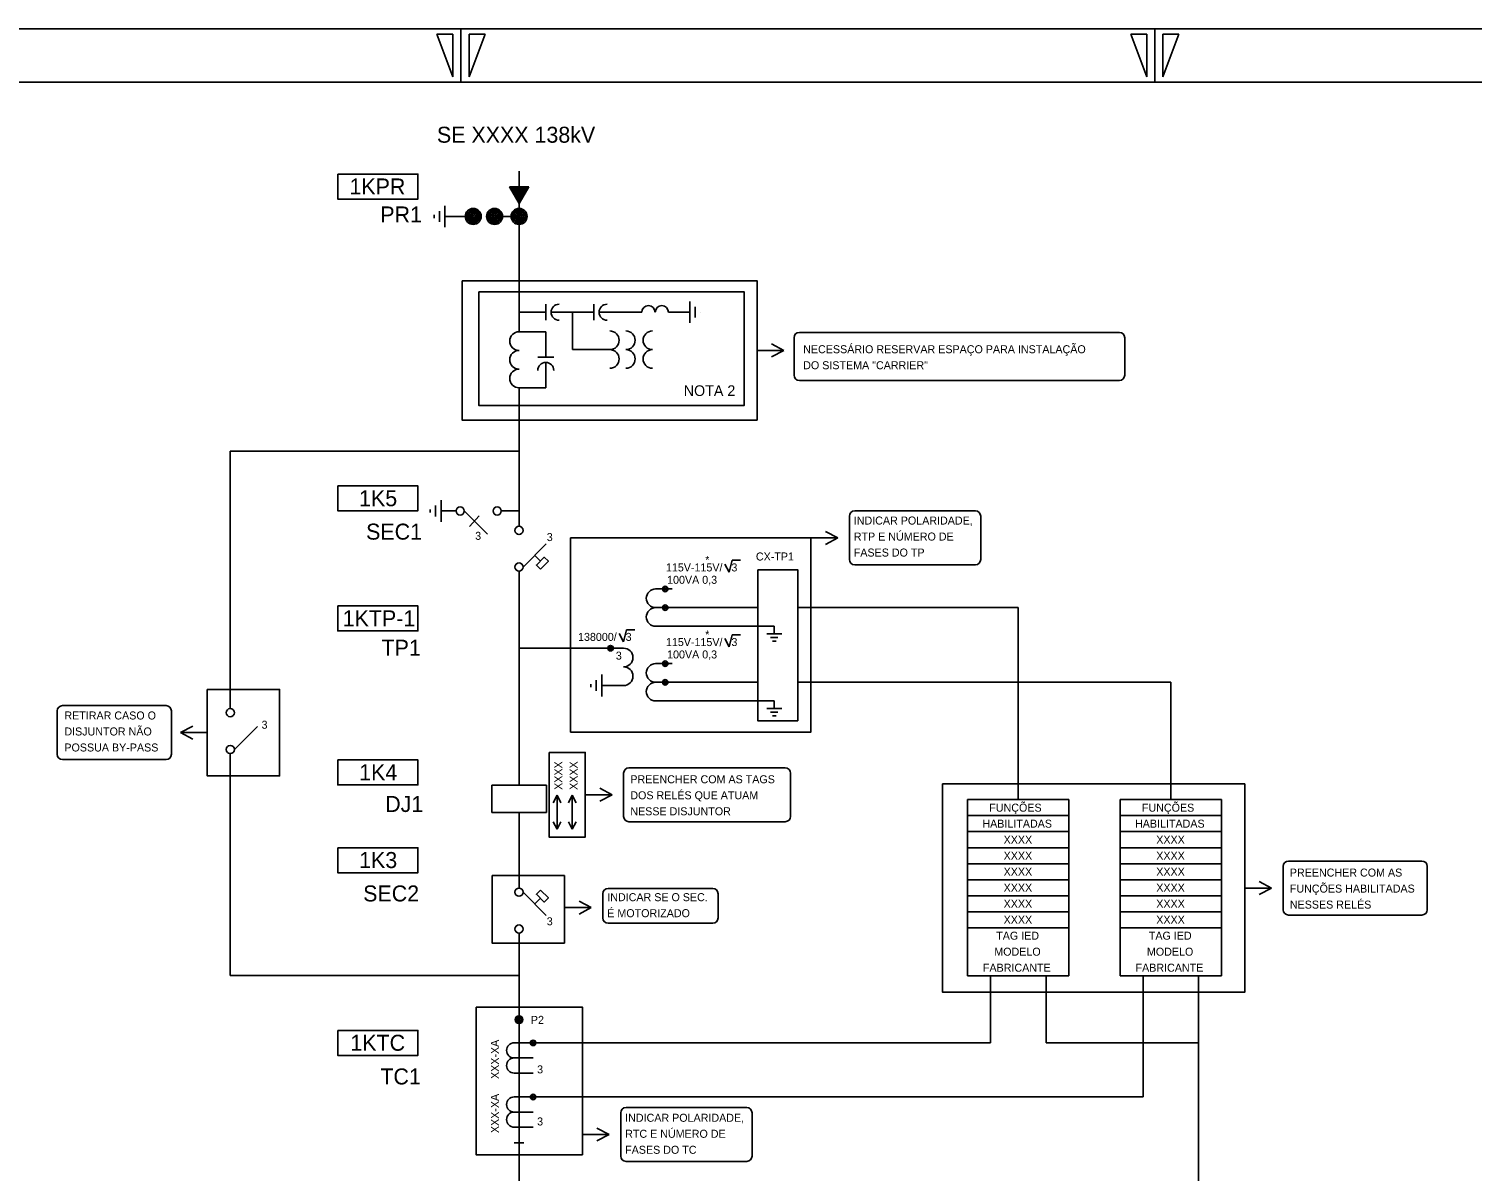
# Model space of a CAD drawing. Extents: x 563 to 1404, y 358 to 952.
# Drawn here: x 822.6 to 1093.1, y 737.8 to 952 of the extents above; entities that cross this region are included whole.
import ezdxf

# ---------------------------------------------------------------- set-up
doc = ezdxf.new("R2010")
doc.units = 0
doc.layers.add('Level 1', color=7, linetype='Continuous')
doc.layers.add('New Level (0)', color=7, linetype='Continuous')

# ---------------------------------------------------------------- blocks, each defined once
blk = doc.blocks.new('_U3')
for p, q in [((-1.47, 0.42), (-0.62, -1.12)), ((-0.62, -1.12), (-0.07, 1.12)), ((-0.07, 1.12), (1.47, 1.12))]:
    blk.add_line(p, q)

msp = doc.modelspace()

# ---------------------------------------------------------------- linework, layer by layer
for p, q in [((914.46, 925.28), (914.46, 895.18)), ((916.27, 922.35), (912.65, 922.35)), ((912.65, 922.35), (914.46, 919.25)), ((916.27, 922.35), (912.65, 922.35)), ((916.08, 922.25), (912.83, 922.25)), ((912.83, 922.25), (914.46, 919.46)), ((914.46, 919.25), (916.27, 922.35)), ((914.46, 922.35), (914.46, 919.25)), ((914.46, 919.46), (916.08, 922.25)), ((915.9, 922.14), (913.01, 922.14)), ((913.01, 922.14), (914.46, 919.67)), ((915.72, 922.04), (913.19, 922.04)), ((913.19, 922.04), (914.46, 919.87)), ((915.54, 921.94), (913.37, 921.94)), ((913.37, 921.94), (914.46, 920.08)), ((915.36, 921.83), (913.55, 921.83)), ((913.55, 921.83), (914.46, 920.29)), ((915.18, 921.73), (913.73, 921.73)), ((913.73, 921.73), (914.46, 920.49)), ((915, 921.63), (913.91, 921.63)), ((913.91, 921.63), (914.46, 920.7)), ((914.82, 921.52), (914.09, 921.52)), ((914.09, 921.52), (914.46, 920.9)), ((914.64, 921.42), (914.27, 921.42)), ((914.27, 921.42), (914.46, 921.11)), ((914.46, 919.67), (915.9, 922.14)), ((914.46, 919.87), (915.72, 922.04)), ((914.46, 920.08), (915.54, 921.94)), ((914.46, 920.29), (915.36, 921.83)), ((914.46, 920.49), (915.18, 921.73)), ((914.46, 920.7), (915, 921.63)), ((914.46, 920.9), (914.82, 921.52)), ((914.46, 921.11), (914.64, 921.42)), ((898.55, 917.1), (898.55, 916.5)), ((899.55, 917.8), (899.55, 915.8)), ((900.55, 914.8), (900.55, 918.8)), ((898.55, 916.8), (898.55, 916.8)), ((901.87, 916.8), (900.55, 916.8)), ((905.87, 916.8), (901.87, 916.8)), ((914.46, 916.8), (909.87, 916.8)), ((914.46, 884.68), (914.46, 858.71)), ((914.46, 872.79), (860.34, 872.79)), ((860.34, 824.54), (860.34, 872.79)), ((899.86, 863.64), (899.86, 859.55)), ((897.82, 861.83), (897.82, 861.3)), ((898.83, 860.57), (898.83, 862.62)), ((902.65, 861.59), (899.86, 861.59)), ((908.52, 857.25), (904.18, 861.59)), ((905.18, 858.65), (906.97, 860.67)), ((914.46, 861.59), (911.13, 861.59)), ((919.56, 855.41), (915.22, 851.07)), ((918.45, 852.18), (917.39, 853.24)), ((914.46, 810.18), (914.46, 850.27)), ((940.05, 846.96), (943.16, 846.96)), ((940.05, 843.46), (959.19, 843.46)), ((966.67, 843.46), (1008, 843.46)), ((940.05, 839.96), (962.28, 839.96)), ((963.68, 838.56), (960.88, 838.56)), ((962.28, 839.96), (962.28, 838.56)), ((914.46, 835.86), (934.05, 835.86)), ((961.58, 837.86), (962.98, 837.86)), ((961.94, 837.16), (962.62, 837.16)), ((940.05, 832.97), (943.16, 832.97)), ((929.96, 830.91), (929.96, 826.82)), ((927.92, 829.1), (927.92, 828.57)), ((928.93, 827.84), (928.93, 829.89)), ((934.05, 828.86), (929.96, 828.86)), ((940.05, 829.47), (943.16, 829.47)), ((940.05, 829.47), (959.19, 829.47)), ((966.67, 829.47), (1036.6, 829.47)), ((940.05, 825.97), (962.28, 825.97)), ((962.28, 825.97), (962.28, 824.57)), ((963.68, 824.57), (960.88, 824.57)), ((961.58, 823.87), (962.98, 823.87)), ((961.94, 823.17), (962.62, 823.17)), ((865.45, 821.2), (861.11, 816.87)), ((860.34, 774.5), (860.34, 816.1)), ((909.34, 805.06), (909.34, 810.18)), ((909.34, 810.18), (919.58, 810.18)), ((919.58, 810.18), (919.58, 805.06)), ((921.57, 808.3), (920.86, 806.88)), ((921.57, 801.93), (921.57, 808.3)), ((921.57, 808.3), (922.28, 806.88)), ((924.42, 808.3), (923.71, 806.88)), ((924.42, 801.93), (924.42, 808.3)), ((924.42, 808.3), (925.13, 806.88)), ((1017.49, 807.47), (998.51, 807.47)), ((998.51, 807.47), (998.51, 774.47)), ((1017.49, 807.47), (1017.49, 774.47)), ((1046.09, 807.47), (1027.11, 807.47)), ((1027.11, 807.47), (1027.11, 774.47)), ((1046.09, 807.47), (1046.09, 774.47)), ((919.58, 805.06), (909.34, 805.06)), ((914.46, 790.89), (914.46, 805.06)), ((921.57, 801.93), (920.86, 803.34)), ((921.57, 801.93), (922.28, 803.34)), ((924.42, 801.93), (923.71, 803.34)), ((924.42, 801.93), (925.13, 803.34)), ((1017.49, 804.47), (998.51, 804.47)), ((1046.09, 804.47), (1027.11, 804.47)), ((1017.49, 801.47), (998.51, 801.47)), ((1046.09, 801.47), (1027.11, 801.47)), ((1017.49, 798.47), (998.51, 798.47)), ((1046.09, 798.47), (1027.11, 798.47)), ((1017.49, 795.47), (998.51, 795.47)), ((1046.09, 795.47), (1027.11, 795.47)), ((1017.49, 792.47), (998.51, 792.47)), ((1046.09, 792.47), (1027.11, 792.47)), ((919.56, 785.78), (915.22, 790.12)), ((918.45, 789.02), (917.39, 787.95)), ((1017.49, 789.47), (998.51, 789.47)), ((1017.49, 789.47), (998.51, 789.47)), ((1046.09, 789.47), (1027.11, 789.47)), ((1046.09, 789.47), (1027.11, 789.47)), ((1017.49, 786.47), (998.51, 786.47)), ((1046.09, 786.47), (1027.11, 786.47)), ((914.46, 680.4), (914.46, 782.45)), ((1017.49, 783.47), (998.51, 783.47)), ((1046.09, 783.47), (1027.11, 783.47)), ((914.46, 774.5), (860.34, 774.5)), ((1017.49, 774.47), (998.51, 774.47)), ((1046.09, 774.47), (1027.11, 774.47)), ((913.55, 761.88), (917.09, 761.88)), ((917.09, 761.88), (1002.8, 761.88)), ((1013.2, 761.88), (1041.8, 761.88)), ((913.55, 759.05), (917.09, 759.05)), ((913.55, 756.22), (917.09, 756.22)), ((913.55, 751.74), (917.09, 751.74)), ((917.09, 751.74), (1031.4, 751.74)), ((913.55, 748.91), (917.09, 748.91)), ((913.55, 746.08), (917.09, 746.08))]:
    msp.add_line(p, q)
for points in [[(918.48, 850.68), (917.72, 851.45), (919.19, 852.92), (919.96, 852.15)], [(918.48, 790.52), (917.72, 789.75), (919.19, 788.28), (919.96, 789.05)]]:
    msp.add_lwpolyline(points, close=True)
for centre, radius in [((905.87, 916.8), 1.5), ((905.87, 916.8), 1.25), ((905.87, 916.8), 1), ((905.87, 916.8), 0.75), ((905.87, 916.8), 0.5), ((905.87, 916.8), 0.25), ((909.87, 916.8), 1.5), ((909.87, 916.8), 1.25), ((909.87, 916.8), 1), ((909.87, 916.8), 0.75), ((909.87, 916.8), 0.5), ((909.87, 916.8), 0.25), ((914.46, 916.8), 1.5), ((914.46, 916.8), 1.25), ((914.46, 916.8), 1), ((914.46, 916.8), 0.75), ((914.46, 916.8), 0.5), ((914.46, 916.8), 0.25), ((903.42, 861.59), 0.768), ((910.36, 861.59), 0.768), ((914.46, 857.94), 0.768), ((914.46, 851.07), 0.768), ((941.85, 846.96), 0.511), ((941.85, 846.96), 0.288), ((941.85, 843.46), 0.511), ((941.85, 843.46), 0.288), ((931.61, 835.86), 0.511), ((931.61, 835.86), 0.288), ((941.85, 832.97), 0.511), ((941.85, 832.97), 0.288), ((941.85, 829.47), 0.511), ((941.85, 829.47), 0.288), ((860.34, 823.77), 0.768), ((860.34, 816.87), 0.768), ((914.46, 790.12), 0.768), ((914.46, 783.22), 0.768), ((914.45, 766.22), 0.729), ((914.46, 766.21), 0.511), ((914.46, 766.21), 0.288), ((917.09, 761.88), 0.511), ((917.09, 761.88), 0.288), ((917.09, 751.74), 0.511), ((917.09, 751.74), 0.288)]:
    msp.add_circle(centre, radius)
for centre, radius, start, end in [((940.05, 845.21), 1.75, 90, 270), ((940.05, 841.71), 1.75, 90, 270), ((934.05, 834.11), 1.75, 270, 90), ((940.05, 831.22), 1.75, 90, 270), ((934.05, 830.61), 1.75, 270, 90), ((940.05, 827.72), 1.75, 90, 270), ((913.55, 760.47), 1.42, 90, 270), ((913.55, 757.63), 1.42, 90, 270), ((913.55, 750.33), 1.42, 90, 270), ((913.55, 747.5), 1.42, 90, 270)]:
    msp.add_arc(centre, radius, start, end)
at = {"layer": 'Level 1'}
for p, q in [((946.46, 900.83), (946.46, 896.83)), ((914.46, 898.83), (919.46, 898.83)), ((919.46, 900.33), (919.46, 897.33)), ((920.46, 898.83), (928.46, 898.83)), ((924.46, 898.83), (924.46, 891.83)), ((928.46, 900.33), (928.46, 897.33)), ((929.46, 898.83), (937.46, 898.83)), ((942.46, 898.83), (946.46, 898.83)), ((947.46, 897.83), (947.46, 899.83)), ((948.46, 898.83), (948.46, 898.83)), ((919.46, 895.18), (914.46, 895.18)), ((919.46, 890.43), (919.46, 895.18)), ((917.96, 890.43), (920.96, 890.43)), ((924.46, 891.83), (931.46, 891.83)), ((919.46, 884.68), (919.46, 889.43)), ((914.46, 884.68), (919.46, 884.68))]:
    msp.add_line(p, q, dxfattribs=at)
for centre, radius, start, end in [((921.96, 898.83), 1.5, 90, 270), ((930.96, 898.83), 1.5, 90, 270), ((938.71, 898.83), 1.25, 0, 180), ((941.21, 898.83), 1.25, 0, 180), ((914.46, 893.43), 1.75, 90, 270), ((931.46, 893.58), 1.75, 270, 90), ((934.46, 893.58), 1.75, 270, 90), ((939.46, 893.58), 1.75, 90, 270), ((914.46, 889.93), 1.75, 90, 270), ((931.46, 890.08), 1.75, 270, 90), ((934.46, 890.08), 1.75, 270, 90), ((939.46, 890.08), 1.75, 90, 270), ((914.46, 886.43), 1.75, 90, 270), ((919.46, 887.93), 1.5, 0, 180)]:
    msp.add_arc(centre, radius, start, end, dxfattribs=at)
at = {"layer": 'New Level (0)'}
for p, q in [((1403.58, 951.96), (562.58, 951.96)), ((1403.58, 951.96), (562.58, 951.96)), ((902.08, 950.96), (899.08, 950.96)), ((899.08, 950.96), (902.08, 942.96)), ((902.08, 942.96), (902.08, 950.96)), ((903.58, 951.96), (903.58, 941.96)), ((905.08, 942.96), (905.08, 950.96)), ((905.08, 950.96), (908.08, 950.96)), ((908.08, 950.96), (905.08, 942.96)), ((1032.08, 950.96), (1029.08, 950.96)), ((1029.08, 950.96), (1032.08, 942.96)), ((1032.08, 942.96), (1032.08, 950.96)), ((1033.58, 951.96), (1033.58, 941.96)), ((1035.08, 942.96), (1035.08, 950.96)), ((1035.08, 950.96), (1038.08, 950.96)), ((1038.08, 950.96), (1035.08, 942.96)), ((1393.58, 941.96), (572.58, 941.96)), ((964.08, 891.68), (961.78, 892.89)), ((965.99, 887.03), (965.99, 894.06)), ((966.99, 895.06), (997.07, 895.06)), ((997.07, 895.06), (1026.95, 895.06)), ((1027.95, 894.06), (1027.95, 887.03)), ((959.05, 891.68), (964.08, 891.68)), ((964.08, 891.68), (961.78, 890.48)), ((1026.95, 886.03), (966.99, 886.03)), ((976.35, 852.49), (976.35, 860.6)), ((977.35, 861.6), (984.7, 861.6)), ((984.7, 861.6), (999.96, 861.6)), ((1000.96, 860.6), (1000.96, 852.49)), ((974.19, 856.54), (971.89, 857.75)), ((969.16, 856.54), (974.19, 856.54)), ((974.19, 856.54), (971.89, 855.33)), ((999.96, 851.49), (977.35, 851.49)), ((1008, 843.46), (1008, 807.47)), ((1036.6, 829.47), (1036.6, 807.47)), ((828.91, 825.1), (832.67, 825.1)), ((832.67, 825.1), (848.31, 825.1)), ((827.91, 815.98), (827.91, 824.1)), ((849.31, 824.1), (849.31, 815.98)), ((851.01, 820.04), (853.31, 821.25)), ((856.04, 820.04), (851.01, 820.04)), ((851.01, 820.04), (853.31, 818.83)), ((848.31, 814.98), (828.91, 814.98)), ((934.05, 804.33), (934.05, 812.44)), ((935.05, 813.44), (942.4, 813.44)), ((942.4, 813.44), (964.34, 813.44)), ((965.34, 812.44), (965.34, 804.33)), ((931.89, 808.39), (929.59, 809.6)), ((926.86, 808.39), (931.89, 808.39)), ((931.89, 808.39), (929.59, 807.18)), ((964.34, 803.33), (935.05, 803.33)), ((1058.63, 795.96), (1065.98, 795.96)), ((1065.98, 795.96), (1083.64, 795.96)), ((1057.63, 786.84), (1057.63, 794.96)), ((1084.64, 794.96), (1084.64, 786.84)), ((930.16, 785.29), (930.16, 789.84)), ((931.16, 790.84), (938.51, 790.84)), ((938.51, 790.84), (950.74, 790.84)), ((951.74, 789.84), (951.74, 785.29)), ((1050.44, 790.9), (1055.47, 790.9)), ((1055.47, 790.9), (1053.17, 792.11)), ((1055.47, 790.9), (1053.17, 789.69)), ((922.97, 787.24), (928, 787.24)), ((928, 787.24), (925.7, 788.45)), ((928, 787.24), (925.7, 786.03)), ((1083.64, 785.84), (1058.63, 785.84)), ((950.74, 784.29), (931.16, 784.29)), ((1002.8, 774.47), (1002.8, 761.88)), ((1013.2, 774.47), (1013.2, 761.88)), ((1031.4, 774.47), (1031.4, 751.74)), ((1041.8, 774.47), (1041.8, 722.12)), ((934.51, 749.77), (941.86, 749.77)), ((941.86, 749.77), (957.12, 749.77)), ((933.51, 740.66), (933.51, 748.77)), ((958.12, 748.77), (958.12, 740.66)), ((926.32, 744.71), (931.35, 744.71)), ((931.35, 744.71), (929.05, 745.92)), ((931.35, 744.71), (929.05, 743.5)), ((913.56, 743.13), (915.36, 743.13)), ((957.12, 739.66), (934.51, 739.66))]:
    msp.add_line(p, q, dxfattribs=at)
for points in [[(880.5, 924.73), (895.52, 924.73), (895.52, 920.04), (880.5, 920.04)], [(903.77, 904.74), (959.05, 904.74), (959.05, 878.63), (903.77, 878.63)], [(906.91, 902.64), (956.67, 902.64), (956.67, 881.36), (906.91, 881.36)], [(880.5, 866.29), (895.52, 866.29), (895.52, 861.61), (880.5, 861.61)], [(924.1, 856.54), (969.16, 856.54), (969.16, 820.13), (924.1, 820.13)], [(959.19, 850.56), (966.67, 850.56), (966.67, 822.27), (959.19, 822.27)], [(880.5, 843.78), (895.52, 843.78), (895.52, 839.09), (880.5, 839.09)], [(856.04, 828.15), (869.6, 828.15), (869.6, 811.93), (856.04, 811.93)], [(880.5, 814.93), (895.52, 814.93), (895.52, 810.24), (880.5, 810.24)], [(920.08, 816.33), (926.86, 816.33), (926.86, 800.44), (920.08, 800.44)], [(993.83, 810.43), (1050.44, 810.43), (1050.44, 771.37), (993.83, 771.37)], [(880.5, 798.44), (895.52, 798.44), (895.52, 793.76), (880.5, 793.76)], [(909.41, 793.24), (922.97, 793.24), (922.97, 780.6), (909.41, 780.6)], [(906.42, 768.58), (926.32, 768.58), (926.32, 740.9), (906.42, 740.9)], [(880.5, 764.22), (895.52, 764.22), (895.52, 759.54), (880.5, 759.54)]]:
    msp.add_lwpolyline(points, close=True, dxfattribs=at)
for centre, start, end in [((966.99, 894.06), 90, 180), ((1026.95, 894.06), 0, 90), ((966.99, 887.03), 180, 270), ((1026.95, 887.03), 270, 0), ((977.35, 860.6), 90, 180), ((999.96, 860.6), 0, 90), ((977.35, 852.49), 180, 270), ((999.96, 852.49), 270, 0), ((828.91, 824.1), 90, 180), ((848.31, 824.1), 0, 90), ((828.91, 815.98), 180, 270), ((848.31, 815.98), 270, 0), ((935.05, 812.44), 90, 180), ((964.34, 812.44), 0, 90), ((935.05, 804.33), 180, 270), ((964.34, 804.33), 270, 0), ((1058.63, 794.96), 90, 180), ((1083.64, 794.96), 0, 90), ((931.16, 789.84), 90, 180), ((950.74, 789.84), 0, 90), ((931.16, 785.29), 180, 270), ((950.74, 785.29), 270, 0), ((1058.63, 786.84), 180, 270), ((1083.64, 786.84), 270, 0), ((934.51, 748.77), 90, 180), ((957.12, 748.77), 0, 90), ((934.51, 740.66), 180, 270), ((957.12, 740.66), 270, 0)]:
    msp.add_arc(centre, 1, start, end, dxfattribs=at)

# ---------------------------------------------------------------- block references
for p in [(954.48, 851.22), (934.67, 838.2), (954.48, 837.23)]:
    msp.add_blockref('_U3', p)

# ---------------------------------------------------------------- texts
for s, height, p in [('SE XXXX 138kV', 3, (899.07, 930.61)), ('1KPR', 3, (882.68, 920.91)), ('PR1', 3, (888.46, 915.66)), ('NECESSÁRIO RESERVAR ESPAÇO PARA INSTALAÇÃO ', 1.5, (967.7, 891.15)), ('DO SISTEMA "CARRIER"', 1.5, (967.7, 888.15)), ('NOTA 2', 2, (945.32, 883.14)), ('1K5', 3, (884.48, 862.47)), ('INDICAR POLARIDADE, ', 1.5, (977.18, 859.04)), ('SEC1', 3, (885.8, 856.21)), ('3', 1.5, (906.24, 856.17)), ('3', 1.5, (919.65, 855.94)), ('RTP E NÚMERO DE ', 1.5, (977.18, 856.04)), ('*', 1.5, (949.34, 851.67)), ('CX-TP1', 1.5, (958.84, 852.3)), ('FASES DO TP', 1.5, (977.18, 853.04)), ('115V-115V/   3', 1.5, (941.98, 850.25)), ('100VA 0,3', 1.5, (942.2, 847.93)), ('1KTP-1', 3, (881.41, 839.96)), ('138000/   3', 1.5, (925.51, 837.23)), ('*', 1.5, (949.34, 837.68)), ('TP1', 3, (888.69, 834.45)), ('115V-115V/   3', 1.5, (941.98, 836.26)), ('3', 1.5, (932.59, 833.72)), ('100VA 0,3', 1.5, (942.2, 833.94)), ('RETIRAR CASO O ', 1.5, (829.26, 822.5)), ('3', 1.5, (866.21, 820.76)), ('DISJUNTOR NÃO ', 1.5, (829.26, 819.5)), ('POSSUA BY-PASS', 1.5, (829.26, 816.5)), ('1K4', 3, (884.5, 811.11)), ('PREENCHER COM AS TAGS ', 1.5, (935.31, 810.54)), ('DOS RELÉS QUE ATUAM ', 1.5, (935.31, 807.54)), ('DJ1', 3, (889.38, 805.16)), ('NESSE DISJUNTOR', 1.5, (935.31, 804.54)), ('FUNÇÕES ', 1.5, (1002.57, 805.22)), ('FUNÇÕES ', 1.5, (1031.17, 805.22)), ('HABILITADAS', 1.5, (1001.28, 802.22)), ('HABILITADAS', 1.5, (1029.88, 802.22)), ('XXXX', 1.5, (1005.26, 799.22)), ('XXXX', 1.5, (1033.86, 799.22)), ('1K3', 3, (884.49, 794.65)), ('XXXX', 1.5, (1005.26, 796.22)), ('XXXX', 1.5, (1033.86, 796.22)), ('XXXX', 1.5, (1005.26, 793.22)), ('XXXX', 1.5, (1033.86, 793.22)), ('PREENCHER COM AS ', 1.5, (1058.89, 793.05)), ('SEC2', 3, (885.25, 788.39)), ('INDICAR SE O SEC. ', 1.5, (930.99, 788.44)), ('XXXX', 1.5, (1005.26, 790.22)), ('XXXX', 1.5, (1033.86, 790.22)), ('FUNÇÕES HABILITADAS ', 1.5, (1058.89, 790.05)), ('É MOTORIZADO', 1.5, (930.99, 785.44)), ('XXXX', 1.5, (1005.26, 787.22)), ('XXXX', 1.5, (1033.86, 787.22)), ('NESSES RELÉS', 1.5, (1058.89, 787.05)), ('3', 1.5, (919.65, 783.92)), ('XXXX', 1.5, (1005.26, 784.22)), ('XXXX', 1.5, (1033.86, 784.22)), ('TAG IED', 1.5, (1003.87, 781.22)), ('TAG IED', 1.5, (1032.47, 781.22)), ('MODELO', 1.5, (1003.51, 778.22)), ('MODELO', 1.5, (1032.11, 778.22)), ('FABRICANTE', 1.5, (1001.38, 775.22)), ('FABRICANTE', 1.5, (1029.98, 775.22)), ('P2', 1.5, (916.67, 765.44)), ('1KTC', 3, (882.85, 760.4)), ('3', 1.5, (917.84, 756.16)), ('TC1', 3, (888.47, 754.08)), ('3', 1.5, (917.84, 746.4)), ('INDICAR POLARIDADE, ', 1.5, (934.34, 747.09)), ('RTC E NÚMERO DE ', 1.5, (934.34, 744.09)), ('FASES DO TC', 1.5, (934.34, 741.09))]:
    msp.add_text(s, height=height).set_placement(p)
for s, p in [('XXXX', (922.57, 809.3)), ('XXXX', (925.42, 809.3)), ('XXX-XA', (910.68, 755.11)), ('XXX-XA', (910.68, 744.97))]:
    msp.add_text(s, height=1.5, rotation=90).set_placement(p)

doc.saveas('drawing.dxf')
